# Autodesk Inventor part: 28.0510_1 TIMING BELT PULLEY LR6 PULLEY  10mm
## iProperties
Created: 2007-06
Part Number: 28.0510_1 TIMING BELT PULLEY LR6 PULLEY  10mm
Document SubType Name: Modeling
Designer: Andy Moles
Material: Aluminum-6061
Density: 2.71 g/cm^3
Author: Andy Moles
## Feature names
1. Revolution1
2. Extrusion1
3. Circular Pattern1
4. Extrusion2
5. Mirror1
6. Extrusion3
